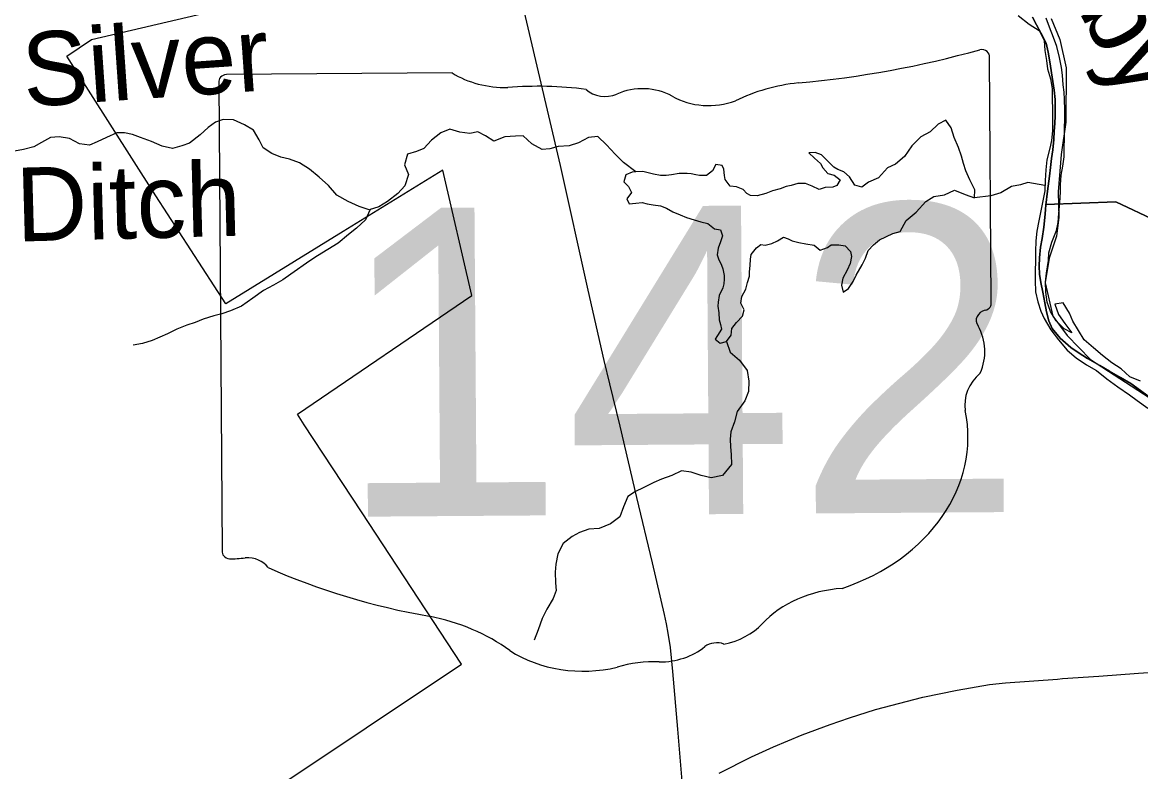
# Model space of a CAD drawing. Extents: x 114604 to 551442, y 316898 to 567001.
# Drawn here: x 130212 to 137786, y 384382 to 389456 of the extents above; entities that cross this region are included whole.
import ezdxf

# ---------------------------------------------------------------- set-up
doc = ezdxf.new("R2010")
doc.units = 0
for name, color, linetype in [('_CIVIL_CONSTRUCTION', 7, 'Continuous'), ('BD_X_Building', 7, 'Continuous'), ('DV_X_County_Line', 7, 'Continuous'), ('GE_P_Alignment_1000_Bearings', 7, 'Continuous'), ('GE_P_Alignment_100_Stations', 7, 'Continuous'), ('GE_P_Alignment_500_Curve_Data', 7, 'Continuous'), ('GE_P_Alignment_500_Distances', 7, 'Continuous'), ('MT_X_Edge_Line', 7, 'Continuous'), ('PM_P_Cells', 7, 'Continuous'), ('PM_P_Stop_Line', 7, 'Continuous'), ('RD_P_GR_Rt', 7, 'Continuous'), ('RS_Raster1', 7, 'Continuous')]:
    doc.layers.add(name, color=color, linetype=linetype)

msp = doc.modelspace()

# ---------------------------------------------------------------- linework, layer by layer
at = {"layer": '_CIVIL_CONSTRUCTION'}
msp.add_lwpolyline([(134887.3, 381784.2), (134852.9, 382241.4), (134820.8, 382652.6), (134798.8, 382912.9), (134763.2, 383389.4), (134692.7, 384181.5), (134651.8, 384669.4), (134617.3, 385059.6), (134600.7, 385222), (134586.5, 385318.8), (134574.8, 385383), (134561, 385446.8), (134479.7, 385796.4), (134372.8, 386239.1), (134260.4, 386720.5), (134190.2, 387007), (134152.8, 387166.4), (134044.7, 387642.6), (133856.7, 388486.2), (133566.8, 389719.1), (133404.8, 390420.3), (133346.7, 390665.9)], dxfattribs=at)
at = {"layer": 'DV_X_County_Line'}
for points in [[(136956.5, 389502.2), (137030.4, 389444), (137098.3, 389399.9), (137132.2, 389333.8), (137136, 389265.7), (137147.9, 389197.6), (137155.8, 389141.6), (137175.6, 389073.5), (137185.5, 389007.4), (137187.4, 388935.3), (137189.2, 388865.2), (137189.1, 388795.1), (137189, 388721.1), (137180.8, 388655), (137170.7, 388603), (137150.6, 388524.9), (137144.4, 388456.8), (137138.3, 388384.8), (137136.2, 388314.7), (137124, 388246.6), (137111.9, 388190.6), (137095.8, 388112.5), (137081.6, 388042.5), (137075.5, 387976.4), (137073.4, 387904.3), (137073.2, 387838.3), (137071.1, 387772.2), (137071, 387708.1), (137072.8, 387632), (137088.7, 387563.9), (137110.6, 387499.8), (137132.5, 387449.7), (137176.3, 387373.6), (137228.2, 387305.5), (137288.1, 387235.3), (137349.9, 387183.2), (137417.8, 387137), (137485.8, 387098.9), (137555.6, 387042.8), (137631.5, 386988.6), (137709.4, 386932.4), (137761.3, 386894.3), (137835.2, 386844.2)], [(137258.5, 388482.7), (137266.6, 388544.8), (137266.7, 388610.8), (137268.8, 388666.9), (137269, 388737), (137271.1, 388803.1), (137271.2, 388863.1), (137269.4, 388933.2), (137267.5, 388983.2), (137261.6, 389033.3), (137255.7, 389097.4), (137249.8, 389149.5), (137235.9, 389217.5), (137218.1, 389291.6), (137196.2, 389353.7), (137168.3, 389423.8), (137146.4, 389483.9)], [(137785.6, 387026.4), (137711.7, 387054.6), (137653.8, 387110.7), (137589.9, 387150.8), (137528, 387199), (137466.1, 387251.1), (137402.2, 387305.2), (137326.4, 387433.5), (137304.5, 387487.6), (137260.7, 387555.7), (137204.7, 387547.8), (137228.5, 387477.7), (137272.4, 387417.5), (137320.3, 387353.4), (137268.3, 387379.5), (137212.5, 387435.6), (137174.6, 387497.7), (137152.7, 387561.8), (137142.8, 387627.9), (137141, 387696), (137149.1, 387758.1), (137161.2, 387844.1), (137163.4, 387896.2), (137183.5, 387968.3), (137215.6, 388046.3), (137227.8, 388100.3), (137231.9, 388162.4), (137238, 388236.5), (137242.2, 388306.5), (137242.3, 388356.6), (137246.4, 388420.7), (137258.5, 388482.7)]]:
    msp.add_lwpolyline(points, dxfattribs=at)
at = {"layer": 'GE_P_Alignment_1000_Bearings'}
msp.add_lwpolyline([(134930.9, 384372.4), (135150.9, 384482.3), (135298.8, 384549.8), (135492.3, 384630.5), (135681.9, 384700.9), (135814.2, 384745.8), (135989.9, 384801.7), (136309.9, 384886.2), (136543.4, 384934.3), (136762.1, 384972.4), (136869.7, 384983), (137222.9, 385008.2), (137256.4, 385011.3), (137503.3, 385028.1), (137770.1, 385047.9), (137936.8, 385060.1)], dxfattribs=at)
at = {"layer": 'GE_P_Alignment_100_Stations'}
for points in [[(131242.5, 383812.5), (133185.7, 385110.4), (132507.9, 386140.3), (132120.1, 386729.4), (132074.4, 386801.7), (133255.1, 387606), (133059.6, 388453.9), (132385.2, 388039.2), (131590.3, 387550.3), (131114.5, 388280.6), (130512.2, 389227.4), (130680.7, 389340.9), (132895.6, 389858.1)], [(137180.7, 389481.3), (137238.1, 389338.9), (137281.6, 389149.1), (137279.2, 388780.9), (137247.2, 388561), (137226.8, 388307.4), (137232.1, 388134.5), (137214.9, 388007.2), (137165.7, 387860), (137145.6, 387735.1), (137141.5, 387709.7), (137138.8, 387692.8), (137190.6, 387465.9), (137288.1, 387335.8), (137445.6, 387173), (138042.2, 386787.5)]]:
    msp.add_lwpolyline(points, dxfattribs=at)
at = {"layer": 'GE_P_Alignment_500_Curve_Data'}
for p, q in [((136774.1, 387560.2), (136762.2, 389218.4)), ((133122.3, 389113.7), (131593.4, 389102.7)), ((131542.4, 389047.8), (131565.2, 385877.8)), ((136773.6, 387560.6), (136774.1, 387560.2))]:
    msp.add_line(p, q, dxfattribs=at)
for centre, major_axis, ratio, start_param, end_param in [((134872, 393448.3), (5536.6, 39.8), 0.800001, 4.814396, 5.04237), ((136704.2, 389224.9), (58.1, 0.4), 0.8, 6.141152, 7.989035), ((131602.1, 389055), (60.5, 0.4), 0.8, 1.712693, 3.28349), ((133483.8, 389484.3), (586.6, 4.2), 0.8, 4.042523, 4.731795), ((133693.7, 387338.1), (2106, 15.1), 0.8, 1.404758, 1.657858), ((134159.3, 389089.8), (169.2, 1.2), 0.8, 3.836095, 5.185415), ((134410.4, 388725.2), (351.9, 2.5), 0.8, 0.950623, 2.079405), ((135616.2, 388163.4), (1113.9, 8), 0.8, 1.699011, 2.107814), ((134860.9, 389231), (423.3, 3), 0.8, 4.081561, 5.145723), ((136712.1, 387553.3), (62.2, 0.4), 0.8, 5.05454, 6.418171), ((136761.5, 387438.3), (89.9, 0.6), 0.8, 1.883978, 3.671073), ((136190.8, 387224.6), (539.9, 3.9), 0.8, 5.934695, 6.695948), ((136987.3, 386867.7), (392.8, 2.8), 0.8, 2.387724, 3.262537), ((135231, 386644.1), (1384.8, 9.9), 0.8, 5.101753, 6.440018), ((131625.5, 385871.3), (61, 0.4), 0.8, 3.00124, 4.508301), ((131632.5, 386195.7), (465.7, 3.3), 0.8, 4.665946, 4.897461), ((131731.3, 385696.1), (167.9, 1.2), 0.8, 0.519207, 1.627899), ((133830.7, 388559.5), (3998.2, 28.7), 0.8, 4.195996, 4.48896), ((135826.6, 385018.4), (758.4, 5.4), 0.8, 1.647645, 2.488433), ((132668.1, 384461.5), (1250.9, 9), 0.8, 0.823519, 1.323588), ((134861.5, 385594.2), (447.4, 3.2), 0.8, 4.937069, 5.64225), ((134530.6, 385463.1), (422.9, 3), 0.8, 4.691044, 5.507374), ((134915.4, 385158.8), (119.1, 0.9), 0.8, 1.147584, 2.315152), ((134012.3, 385696.8), (793.8, 5.7), 0.8, 4.026481, 4.996735), ((134478.8, 384604.1), (652.3, 4.7), 0.8, 1.495662, 1.94098)]:
    msp.add_ellipse(centre, major_axis=major_axis, ratio=ratio, start_param=start_param, end_param=end_param, dxfattribs=at)
at = {"layer": 'GE_P_Alignment_500_Distances'}
for points in [[(137054.1, 389491.2), (137080.3, 389439.1), (137110.5, 389384.9), (137144.8, 389314.7), (137158.9, 389254.5), (137171.1, 389188.3), (137191.3, 389055.8), (137199.5, 388997.6), (137205.6, 388933.4), (137207.6, 388875.2), (137205.7, 388823), (137203.8, 388770.8), (137199.8, 388718.6), (137197.8, 388662.3), (137189.9, 388592), (137181.9, 388533.8), (137176, 388473.6), (137168, 388413.3), (137160, 388347), (137152.1, 388294.8), (137146.1, 388236.6), (137144.4, 388222.6), (137140.1, 388186.4), (137136.1, 388134.2), (137130.2, 388069.9), (137118.2, 387991.6), (137108.3, 387933.3), (137100.3, 387861), (137098.4, 387804.8), (137100.4, 387750.6), (137108.5, 387694.4), (137122.7, 387628.2), (137136.9, 387555.9), (137149, 387495.7), (137163.2, 387435.5), (137187.3, 387383.4), (137239.7, 387317.3), (137312.2, 387253.2), (137362.5, 387221.2), (137424.9, 387179.1), (137509.4, 387133.2), (137575.8, 387093.2), (137648.3, 387051.2), (137718.7, 387011.2), (137785.1, 386963.2), (137837.4, 386925.2)], [(137894.4, 388109), (137617.9, 388240.6), (137144.4, 388222.6), (137146.1, 388236.6), (137152.1, 388294.8), (137160, 388347), (137168, 388413.3), (137176, 388473.6), (137181.9, 388533.8), (137189.9, 388592), (137197.8, 388662.3), (137199.8, 388718.6), (137203.8, 388770.8), (137205.7, 388823), (137207.6, 388875.2), (137205.6, 388933.4), (137199.5, 388997.6), (137191.3, 389055.8), (137171.1, 389188.3), (137158.9, 389254.5), (137144.8, 389314.7), (137110.5, 389384.9), (137080.3, 389439.1), (137054.1, 389491.2)], [(137837.4, 386925.2), (137785.1, 386963.2), (137718.7, 387011.2), (137648.3, 387051.2), (137575.8, 387093.2), (137509.4, 387133.2), (137424.9, 387179.1), (137362.5, 387221.2), (137312.2, 387253.2), (137239.7, 387317.3), (137187.3, 387383.4), (137163.2, 387435.5), (137149, 387495.7), (137136.9, 387555.9), (137122.7, 387628.2), (137108.5, 387694.4), (137100.4, 387750.6), (137098.4, 387804.8), (137100.3, 387861), (137108.3, 387933.3), (137118.2, 387991.6), (137130.2, 388069.9), (137136.1, 388134.2), (137140.1, 388186.4), (137144.4, 388222.6), (137617.9, 388240.6), (137894.4, 388109)]]:
    msp.add_lwpolyline(points, dxfattribs=at)
at = {"layer": 'MT_X_Edge_Line'}
for points in [[(136017.5, 387984.3), (136107.2, 388026.1), (136157.1, 388040.4), (136196.7, 388114.7), (136264.4, 388171), (136330.1, 388243.4), (136385.9, 388275.7), (136457.8, 388288.1), (136525.6, 388320.5), (136597.7, 388290.8), (136659.7, 388267.1), (136661.5, 388321.1), (136629.2, 388389), (136601, 388451), (136584.8, 388500.9), (136572.6, 388550.9), (136552.3, 388608.9), (136522, 388676.8), (136501.7, 388742.8), (136465.5, 388792.7), (136413.7, 388766.4), (136360, 388714.1), (136296.1, 388681.7), (136236.5, 388619.4), (136186.8, 388547), (136125.1, 388494.7), (136071.2, 388470.4), (136011.1, 388402.3)], [(136011.1, 388402.3), (135941.8, 388372.9), (135897.8, 388340.9), (135849.8, 388352.9), (135813.9, 388409), (135775.9, 388443.1), (135734, 388459.1), (135708, 388475.1), (135664, 388517.2), (135624.1, 388559.3), (135582.1, 388575.3), (135538.2, 388571.3), (135576.1, 388535.3), (135618.1, 388499.2), (135634, 388471.2), (135666, 388433.1), (135710, 388421.1), (135749.9, 388389), (135727.9, 388350.9), (135701.9, 388338.9), (135649.9, 388336.9), (135608, 388324.9), (135560, 388347), (135516, 388365), (135464.1, 388365.1), (135418.1, 388351), (135384.1, 388345), (135344.1, 388329), (135292.1, 388315), (135246.1, 388297), (135188.2, 388281), (135144.2, 388283), (135118.2, 388297.1), (135094.3, 388323.1), (135048.3, 388341.2), (135006.3, 388347.2), (134972.4, 388391.3), (134966.4, 388419.3), (134962.4, 388461.4), (134950.4, 388487.4), (134908.5, 388493.4), (134886.4, 388449.4), (134844.5, 388419.4), (134798.5, 388419.4)], [(134798.5, 388419.4), (134772.5, 388423.4), (134740.5, 388429.4), (134714.5, 388433.4), (134686.6, 388431.4), (134660.6, 388431.4), (134608.6, 388423.4), (134572.6, 388419.4), (134532.6, 388419.5), (134486.7, 388427.5), (134440.7, 388439.5), (134414.7, 388445.5), (134366.7, 388443.5), (134340.8, 388441.6), (134298.8, 388423.5), (134284.7, 388375.5), (134316.7, 388343.4), (134336.7, 388303.3), (134306.7, 388261.3), (134320.6, 388227.2), (134366.6, 388231.2), (134410.6, 388235.2), (134442.6, 388227.2), (134484.5, 388219.2), (134534.5, 388213.1), (134574.5, 388197.1), (134616.4, 388173), (134666.4, 388153), (134710.3, 388135), (134762.3, 388118.9), (134806.3, 388104.9), (134854.2, 388094.8), (134900.2, 388056.8), (134940.2, 388050.8), (134954.1, 388010.7), (134940.1, 387970.6), (134924.1, 387926.6), (134918.1, 387880.5), (134926, 387854.5), (134946, 387812.4), (134956, 387786.3), (134963.9, 387742.3), (134963.9, 387716.2), (134961.9, 387684.2), (134955.9, 387658.1), (134931.9, 387606.1), (134923.8, 387560), (134921.8, 387534), (134927.8, 387489.9), (134931.8, 387441.8), (134939.7, 387409.8), (134945.7, 387377.7), (134919.7, 387335.6), (134903.7, 387309.6), (134937.7, 387283.6), (134979.6, 387293.6), (135011.7, 387337.6), (135015.7, 387383.7), (135047.7, 387423.7), (135089.7, 387465.8), (135099.7, 387509.9), (135077.8, 387553.9), (135083.8, 387600), (135111.8, 387648.1), (135121.8, 387694.1), (135135.9, 387736.2), (135135.9, 387766.2), (135141.9, 387810.3), (135143.9, 387852.4), (135147.9, 387884.4), (135183.9, 387928.5), (135213.9, 387952.5), (135241.9, 387946.5), (135287.9, 387958.5), (135325.9, 387976.5), (135365.9, 388000.5), (135397.9, 387990.5), (135425.8, 387976.5), (135469.8, 387964.4), (135517.8, 387956.4), (135573.7, 387946.4), (135615.7, 387912.3), (135663.7, 387932.3), (135689.7, 387948.3), (135741.6, 387950.3), (135783.6, 387942.3), (135819.6, 387904.2), (135827.5, 387870.2), (135817.5, 387822.1), (135797.5, 387778), (135769.5, 387724), (135759.5, 387675.9), (135771.4, 387627.8), (135807.4, 387653.8), (135839.4, 387699.9), (135859.4, 387744), (135899.5, 387814.1), (135921.5, 387860.1), (135939.5, 387910.2), (135975.5, 387950.2), (136017.5, 387984.3)]]:
    msp.add_lwpolyline(points, dxfattribs=at)
at = {"layer": 'PM_P_Cells'}
for points in [[(134366.7, 388443.5), (134282.8, 388507.7), (134226.9, 388563.8), (134169, 388625.9), (134109, 388682), (134047.1, 388676), (133979.1, 388640), (133915.1, 388620), (133841.2, 388616), (133785.2, 388600), (133733.2, 388596), (133663.3, 388634.1), (133603.3, 388688.2), (133551.4, 388686.2), (133479.4, 388680.2), (133405.4, 388652.2), (133349.5, 388688.3), (133295.5, 388714.3), (133241.5, 388702.3), (133173.6, 388712.4), (133107.7, 388732.4), (133045.7, 388708.4), (132981.7, 388658.4), (132931.7, 388602.3), (132881.7, 388580.3), (132819.7, 388562.3), (132799.7, 388492.2), (132827.6, 388426), (132801.6, 388349.9), (132755.6, 388295.9), (132685.6, 388241.8), (132625.6, 388205.8), (132559.6, 388185.8), (132491.7, 388209.8), (132417.7, 388241.9), (132341.8, 388286), (132285.9, 388352.1), (132221.9, 388408.2), (132156, 388462.3), (132088.1, 388504.4), (132020.1, 388528.5), (131962.2, 388542.5), (131902.2, 388568.6), (131842.3, 388606.7), (131816.3, 388660.8), (131776.4, 388724.9), (131716.5, 388763), (131642.5, 388795), (131572.6, 388797.1), (131520.6, 388781), (131470.6, 388745), (131416.6, 388695), (131344.6, 388638.9), (131292.6, 388620.9), (131228.6, 388600.9), (131158.7, 388616.9), (131086.7, 388649), (131010.8, 388677.1), (130956.8, 388697.1), (130902.9, 388707.2), (130850.9, 388707.2), (130780.9, 388677.1), (130718.9, 388647.1), (130667, 388625.1), (130599, 388633.1), (130531.1, 388669.2), (130461.1, 388681.3), (130401.1, 388675.3), (130341.1, 388643.2), (130289.2, 388613.2), (130219.2, 388595.2), (130159.2, 388583.2)], [(137137.3, 388351.1), (137021.1, 388370.9), (136971.2, 388356.7), (136911.2, 388344.4), (136839.5, 388302), (136771.6, 388281.6), (136659.7, 388267.1)], [(132567.9, 388188.3), (132535.6, 388117.7), (132473.6, 388061.6), (132421.6, 388019.6), (132351.6, 387961.5), (132279.6, 387917.5), (132211.6, 387875.4), (132159.6, 387841.4), (132029.6, 387751.3), (131975.6, 387713.3), (131911.6, 387677.2), (131845.7, 387639.2), (131771.7, 387587.1), (131695.7, 387535.1), (131621.7, 387503), (131563.7, 387483), (131507.7, 387469), (131435.8, 387445), (131381.8, 387423), (131325.8, 387405), (131257.8, 387379), (131193.8, 387347), (131141.8, 387324.9), (131089.9, 387300.9), (131025.9, 387280.9), (130961.9, 387268.9)], [(134979.6, 387293.6), (135005.6, 387223.4), (135069.5, 387167.3), (135121.4, 387099.2), (135131.4, 387027.1), (135129.3, 386957), (135105.3, 386892.9), (135053.3, 386820.8), (135035.3, 386750.7), (135009.2, 386682.6), (135005.2, 386632.5), (135007.2, 386580.4), (135013.1, 386528.4), (135015.1, 386462.2), (134953.1, 386388.2), (134877.1, 386372.2), (134809.2, 386386.2), (134741.2, 386410.3), (134675.3, 386418.3), (134611.3, 386386.3), (134539.3, 386362.3), (134489.3, 386340.2), (134417.3, 386304.2), (134363.3, 386278.2), (134311.3, 386244.1), (134283.3, 386176.1), (134259.3, 386108), (134195.3, 386059.9), (134117.3, 386027.9), (134047.3, 386023.9), (133985.4, 386001.9), (133935.4, 385973.9), (133873.4, 385927.8), (133839.4, 385857.7), (133825.3, 385787.6), (133821.3, 385731.5), (133823.2, 385659.4), (133827.2, 385609.3), (133807.2, 385555.2), (133763.1, 385481.1), (133733.1, 385419), (133705.1, 385342.9), (133679, 385272.8)]]:
    msp.add_lwpolyline(points, dxfattribs=at)
at = {"layer": 'RS_Raster1'}
for points in [[(137054.1, 389491.2), (137080.3, 389439.1), (137110.5, 389384.9), (137144.8, 389314.7), (137158.9, 389254.5), (137171.1, 389188.3), (137191.3, 389055.8), (137199.5, 388997.6), (137205.6, 388933.4), (137207.6, 388875.2), (137205.7, 388823), (137203.8, 388770.8), (137199.8, 388718.6), (137197.8, 388662.3), (137189.9, 388592), (137181.9, 388533.8), (137176, 388473.6), (137168, 388413.3), (137160, 388347), (137152.1, 388294.8), (137146.1, 388236.6), (137144.4, 388222.6), (137140.1, 388186.4), (137136.1, 388134.2), (137130.2, 388069.9), (137118.2, 387991.6), (137108.3, 387933.3), (137100.3, 387861), (137098.4, 387804.8), (137100.4, 387750.6), (137108.5, 387694.4), (137122.7, 387628.2), (137136.9, 387555.9), (137149, 387495.7), (137163.2, 387435.5), (137187.3, 387383.4), (137239.7, 387317.3), (137312.2, 387253.2), (137362.5, 387221.2), (137424.9, 387179.1), (137509.4, 387133.2), (137575.8, 387093.2), (137648.3, 387051.2), (137718.7, 387011.2), (137785.1, 386963.2), (137837.4, 386925.2)], [(137837.4, 386925.2), (137785.1, 386963.2), (137718.7, 387011.2), (137648.3, 387051.2), (137575.8, 387093.2), (137509.4, 387133.2), (137424.9, 387179.1), (137362.5, 387221.2), (137312.2, 387253.2), (137239.7, 387317.3), (137187.3, 387383.4), (137163.2, 387435.5), (137149, 387495.7), (137136.9, 387555.9), (137122.7, 387628.2), (137108.5, 387694.4), (137100.4, 387750.6), (137098.4, 387804.8), (137100.3, 387861), (137108.3, 387933.3), (137118.2, 387991.6), (137130.2, 388069.9), (137136.1, 388134.2), (137140.1, 388186.4), (137144.4, 388222.6), (137146.1, 388236.6), (137152.1, 388294.8), (137160, 388347), (137168, 388413.3), (137176, 388473.6), (137181.9, 388533.8), (137189.9, 388592), (137197.8, 388662.3), (137199.8, 388718.6), (137203.8, 388770.8), (137205.7, 388823), (137207.6, 388875.2), (137205.6, 388933.4), (137199.5, 388997.6), (137191.3, 389055.8), (137171.1, 389188.3), (137158.9, 389254.5), (137144.8, 389314.7), (137110.5, 389384.9), (137080.3, 389439.1), (137054.1, 389491.2)]]:
    msp.add_lwpolyline(points, dxfattribs=at)

# ---------------------------------------------------------------- texts
at = {"layer": 'BD_X_Building'}
for s, p in [('r', (134107.4, 387271.4)), ('s', (134107.4, 387271.4)), ('142', (133754.9, 387196.1))]:
    msp.add_text(s, height=1, rotation=0.41161, dxfattribs=at).set_placement(p)
at = {"layer": 'GE_P_Alignment_500_Curve_Data'}
msp.add_text('142', height=2088.4, rotation=0.41161, dxfattribs=at).set_placement((132339.6, 386106.9))
at = {"layer": 'PM_P_Stop_Line'}
for s, rotation, p in [('Silver', 3.97389, (130227.9, 388882.2)), ('Ditch', 1.52891, (130174, 387971))]:
    msp.add_text(s, height=500.02, rotation=rotation, dxfattribs=at).set_placement(p)
at = {"layer": 'RD_P_GR_Rt'}
msp.add_text('Darby', height=499.98, rotation=298.24376, dxfattribs=at).set_placement((136851.5, 390485.5))

doc.saveas('drawing.dxf')
